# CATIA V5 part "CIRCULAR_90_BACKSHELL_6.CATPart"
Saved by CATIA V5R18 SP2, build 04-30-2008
Part number: CIRCULAR_90_BACKSHELL_6
Revision: ---
Publications: "Logical Termination.1", "Face_generated(BaCP)", "Axis_generated(BaCP)", "Face_generated(BaCP).1", "BCPRPoint_generated(BCP)", "BCPRPlane_generated(BCP)", "SOCKRLine_generated(Sock)", "BaCP", "BCP", "SOCK", "SOCKRPoint_generated(SOCK)"
Bounding box of the stored display mesh (mm): x 0 to 36.271, y -12.446 to 12.446, z -27.432 to 10.312
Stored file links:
  C:\Users\ajc8720\Documents\BOEING_WORK\0001-2CES\004-AP242\Boeing-Generic_Harness_R3\CIRCULAR_90_BACKSHELL_6.CATPart
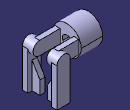
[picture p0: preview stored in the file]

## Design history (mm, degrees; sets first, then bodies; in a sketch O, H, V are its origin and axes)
Parameters
  PartNumber = "CIRCULAR_90_BACKSHELL_6"
Set1 "EGF"
  Set2 "BCP"
    Point1 "BCPRPoint": type Between, FirstPoint vertex [face of Pocket1 from Sketch5.L4 | start face of Pad3 | face of Pad3 from Sketch4.L2], SecondPoint vertex [face of Mirror1 | face of Mirror1 | face of Mirror1], Ratio 0.5
    Plane1 "BCPRPlane": type OffsetPt, RefPlane face of Mirror1, RefPoint Point1
  Set3 "BaCP"
    Plane2 "BaCCPlane": type Offset, RefPlane yz-plane, Offset 7.62 {= deleted_LENGTH}
    Point2 "BaCPRPoint": type OnPlane, Support Plane2, H 0, V 0, Direction (0, 1, 0)
  Set4 "SOCK"
    Point3 "SOCKRPoint": type OnSurface, Support face of Pad3 from Sketch4.L2, Length 0, Direction (-0.2017, 0.9757, -0.0856)
    Line1 "SOCKRLine": type PtDir, RefPoint Point3, Direction edge [start face of Pad3 | face of Pocket1 from Sketch5.L4], Start 0, End 6.35
Set5 "ConstructionGeometry"
  Plane3: type Offset, RefPlane zx-plane, Offset -4.8768 {= -( deleted_LENGTH / 2 )}
Body1 (main body)
  Sketch1 on yz-plane, origin (0, 0, 0), H (0, 1, 0), V (0, 0, 1)
    circle A1 centre (0, 0) radius 7.62
    radius A1 = 7.62
  Pad1: profile Sketch1, direction (1, 0, 0), length 1.4478 {= deleted_LENGTH}
  Sketch2 on end face of Pad1, origin (1.4478, 0, 0), H (0, 1, 0), V (0, 0, 1)
    circle A1 centre (0, 0) radius 10.3124
    radius A1 = 10.3124
  Pad2: profile Sketch2, direction (1, 0, 0), length 15.3162 {= deleted_LENGTH-deleted_LENGTH}
  Sketch3 on start face of Pad1, origin (0, 0, 0), H (0, 1, 0), V (0, 0, -1)
    point P1 (0, 0)
    coincidence: P1 O
  Hole1: placed by Sketch3, at (0, 0, 0) direction (1, 0, 0), diameter 6.7056 {= deleted_LENGTH}, depth 16.764 {= deleted_LENGTH}, counterbore diameter 11.9888 {= deleted_LENGTH}, counterbore depth 7.62 {= deleted_LENGTH}
  Sketch4 on zx-plane, origin (0, 0, 0), H (1, 0, 0), V (0, 0, -1)
    line L1 (26.7208, 0) -> (26.7208, 27.432)
    line L2 (26.7208, 27.432) -> (36.2712, 27.432)
    line L3 (36.2712, 27.432) -> (36.2712, 0)
    arc A1 centre (31.496, 0) radius 4.7752 from (36.2712, 0) to (26.7208, 0) cw
    point P4 (31.496, 0)
    distance P4 V = 31.496
    distance L1 L3 = 9.5504
    distance P4 L2 = 27.432
    angle H L1 = 90
    tangency: A1 L1, A1 L3
    parallelism: L3 L1
    coincidence: P4 H
    perpendicularity: L2 L1
  Pad3: profile Sketch4, direction (0, -1, 0), length 12.446 {= deleted_LENGTH/2}, opposite side length -2.794 {= -deleted_LENGTH/2}
  Sketch5 on start face of Pad3, origin (0, -2.794, 5.588), H (1, 0, 0), V (0, 0, -1)
    line L1 (26.7208, 33.02) -> (26.7208, 5.588)
    arc A1 centre (31.496, 5.588) radius 4.7752 from (26.7208, 5.588) to (36.2712, 5.588) ccw
    line L2 (36.2712, 5.588) -> (36.2712, 33.02)
    point P5 (36.2712, 33.02)
    line L3 (29.6926, 33.02) -> (26.7208, 33.02)
    line L4 (33.2994, 13.97) -> (33.2994, 33.02)
    line L5 (29.6926, 33.02) -> (29.6926, 13.97)
    line L6 (29.6926, 13.97) -> (33.2994, 13.97)
    reference projected line E1 (26.7208, 33.1839) -> (26.7208, 5.7519) from Sketch4.L1
    reference projected line E2 (193.5727, 33.02) -> (184.0223, 33.02) from Sketch4.L2
    reference projected line E3 (36.2712, -40.4085) -> (36.2712, -12.9765) from Sketch4.L3
    reference projected arc E4 centre (31.496, 5.588) radius 4.7752 from (31.496, 10.3632) to (31.496, 0.8128) ccw from Sketch4.A1
    line L7 (36.2712, 33.02) -> (33.2994, 33.02)
    distance L5 L1 = 2.9718
    length L7 = 2.9718
    length L4 = 19.05
    tangency: A1 L1, L2 A1
    coincidence: L1 E1, E2 L3, E3 L2, A1 E4, P5 L3
    parallelism: L5 L1, L4 L2, L6 L3, L7 L6
  Pocket1: profile Sketch5, direction (0, -1, 0), length 5.6896 {= deleted_LENGTH/2 - deleted_LENGTH/2 + deleted_LENGTH}
  Sketch6 on face of Pocket1 from Sketch5.L5, origin (29.6926, -3.6068, -46.5314), H (0, 0, -1), V (0, -1, 0)
    point P1 (-38.1494, 4.8768)
    line L1 (-38.1494, 4.8768) -> (-28.6244, -0.8128)
    point P2 (-28.6244, -0.8128)
    line L2 (-28.6244, -0.8128) -> (-38.1494, -0.8128)
    line L3 (-38.1494, -0.8128) -> (-38.1494, 4.8768)
    reference projected line E1 (-38.1494, 2.794) -> (-38.1494, 8.4836) from edge [face of Pocket1 from Sketch5.L6 | face of Pocket1 from Sketch5.L5]
    reference projected line E2 (42.6969, -0.8128) -> (58.928, -0.8128) from edge [start face of Pad3 | face of Pocket1 from Sketch5.L5]
    reference projected line E3 (58.928, 4.8768) -> (31.496, 4.8768) from edge [face of Pad3 from Sketch4.L1 | end face of Pocket1]
    reference projected line E4 (-19.0994, 2.794) -> (-19.0994, 8.4836) from edge [face of Pad3 from Sketch4.L2 | face of Pocket1 from Sketch5.L5]
    distance P2 E4 = 9.525
    coincidence: L3 E1, L2 E2, P1 E3
  Pocket2: profile Sketch6, direction (1, 0, 0), through (limit type 6)
  Sketch7 on Plane3, origin (0, -4.8768, 9.7536), H (1, 0, 0), V (0, 0, 1)
    line L1 (16.764, -14.5288) -> (31.496, -14.5288)
    line L2 (31.496, -4.9784) -> (16.764, -4.9784)
    line L3 (16.764, -4.9784) -> (16.764, -14.5288)
    arc A1 centre (31.496, -9.7536) radius 4.7752 from (31.496, -4.9784) to (31.496, -14.5288) cw
    point P5 (31.496, -9.7536)
    reference intersected line E1 through (0, -9.7536) direction (-1, 0) from xy-plane
    distance V L3 = 16.764
    distance L2 L1 = 9.5504
    distance P5 V = 31.496
    horizontal: L1 H, L2 H
    vertical: L3 V
    symmetry: L1 L2 E1
    tangency: A1 L2, A1 L1
  Pad4: profile Sketch7, direction (0, -1, 0), length 3.6068 {= deleted_LENGTH}
  Mirror1: of Pad3, Sketch4, Pocket1, Sketch5, Pocket2, Sketch6, Pad4, Sketch7, about zx-plane
Body2 "BaCP"
  Sketch8 on Plane2, origin (7.62, 0, 0), H (0, 1, 0), V (0, 0, 1)
    arc A1 centre (0, 0) radius 1.016 from (-0.672, 0.762) to (0.672, 0.762) ccw
    line L1 (-0.672, 0.762) -> (0.672, 0.762)
    distance L1 H = 0.762
    radius A1 = 1.016
  Pad5: profile Sketch8, direction (1, 0, 0), length 0.508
